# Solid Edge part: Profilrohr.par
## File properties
Username: bmolnar
Dokumentum tartalom típus: 0
Author: bmolnar
Last saved by: bmolnar
Revision: 76
Sűrűség: 0,000 kg/m^3
Pontosság: 0,990
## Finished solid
Body 1: solid body, 115 faces, 338 edges, 224 vertices.
  Faces by surface: cylinder 59, plane 56
  Edges by curve: line 220, circle 118
Bounding box of the edges (mm): 77.000 x 77.000 x 26.500, from (-38.5, -38.5, 0) to (38.5, 38.5, 26.5).
Cylindrical faces by radius (mm): R0.15 x24, R0.25 x24, R1 x4, R12 x4, R13.5 x2, R31.5 x1
Planar faces by outward normal: +x 13, +y 14, +z 1, -x 13, -y 14, -z 1
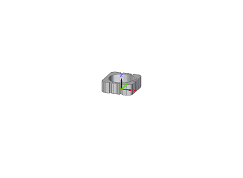
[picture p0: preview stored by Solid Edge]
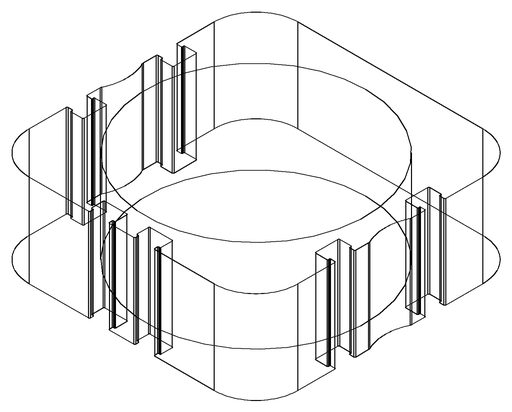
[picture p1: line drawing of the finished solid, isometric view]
